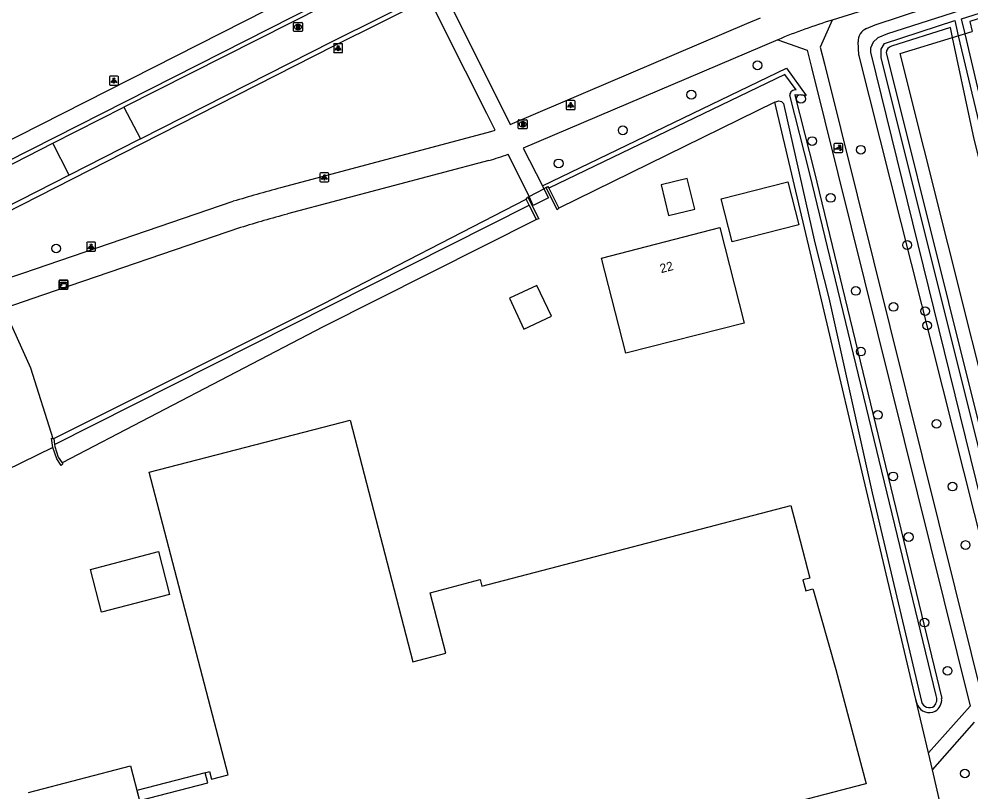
# Model space of a CAD drawing. Extents: x 162880 to 165536, y 384011 to 385179.
# Drawn here: x 163466 to 163572.4, y 384360.2 to 384446.6 of the extents above; entities that cross this region are included whole.
import ezdxf

# ---------------------------------------------------------------- set-up
doc = ezdxf.new("R2010")
doc.units = 0
for name, color, linetype in [('IMGEO_Boom', 7, 'Continuous'), ('IMGEO_Brandkraan', 7, 'Continuous'), ('IMGEO_Erf', 7, 'Continuous'), ('IMGEO_Groenvoorziening', 7, 'Continuous'), ('IMGEO_Hek', 7, 'Continuous'), ('IMGEO_Kast', 7, 'Continuous'), ('IMGEO_Lichtpunt', 7, 'Continuous'), ('IMGEO_Loofbos', 7, 'Continuous'), ('IMGEO_Muur', 7, 'Continuous'), ('IMGEO_Pand', 7, 'Continuous'), ('IMGEO_Pand_nummerreeks', 7, 'Continuous'), ('IMGEO_Pand_overbouw', 7, 'Continuous'), ('IMGEO_Poller', 7, 'Continuous'), ('IMGEO_Rijbaan_lokaal_gesloten', 7, 'Continuous'), ('IMGEO_Rijbaan_lokaal_open', 7, 'Continuous'), ('IMGEO_Rioolput', 7, 'Continuous'), ('IMGEO_Voetpad_open', 7, 'Continuous'), ('IMGEO_Waterloop', 7, 'Continuous')]:
    doc.layers.add(name, color=color, linetype=linetype)

msp = doc.modelspace()

# ---------------------------------------------------------------- linework, layer by layer
at = {"layer": 'IMGEO_Boom'}
for centre in [(163548.54, 384441.38), (163541.14, 384438.1), (163553.39, 384437.65), (163533.48, 384434.12), (163554.64, 384432.92), (163560.07, 384431.95), (163526.32, 384430.42), (163556.71, 384426.56), (163470.19, 384420.91), (163565.24, 384421.3), (163559.51, 384416.17), (163563.73, 384414.38), (163567.26, 384413.91), (163567.49, 384412.3), (163560.09, 384409.39), (163561.97, 384402.31), (163568.54, 384401.32), (163563.7, 384395.44), (163570.31, 384394.3), (163565.42, 384388.67), (163571.78, 384387.77), (163567.18, 384379.1), (163569.77, 384373.71), (163571.7, 384362.23)]:
    msp.add_circle(centre, 0.489, dxfattribs=at)
at = {"layer": 'IMGEO_Brandkraan'}
for p, q in [((163521.81, 384434.36), (163521.81, 384435.22)), ((163521.88, 384435.29), (163522.74, 384435.29)), ((163522.3, 384435.07), (163522.32, 384435.07)), ((163522.81, 384435.22), (163522.81, 384434.36)), ((163522.74, 384434.29), (163521.88, 384434.29)), ((163522.32, 384434.51), (163522.29, 384434.51))]:
    msp.add_line(p, q, dxfattribs=at)
for points in [[(163521.81, 384434.36), (163521.81, 384435.22)], [(163521.88, 384435.29), (163522.74, 384435.29)], [(163522.16, 384434.99), (163522.16, 384434.59), (163522.37, 384434.59)], [(163522.39, 384434.99), (163522.16, 384434.99)], [(163522.33, 384434.91), (163522.28, 384434.91), (163522.28, 384434.83)], [(163522.81, 384435.22), (163522.81, 384434.36)], [(163522.74, 384434.29), (163521.88, 384434.29)], [(163522.28, 384434.83), (163522.33, 384434.83)], [(163522.34, 384434.76), (163522.28, 384434.76), (163522.28, 384434.68)], [(163522.28, 384434.68), (163522.34, 384434.68)]]:
    msp.add_lwpolyline(points, dxfattribs=at)
for centre, radius, start, end in [((163521.88, 384435.22), 0.0765, 91.552, 178.448), ((163521.88, 384435.22), 0.0765, 91.552, 178.448), ((163522.34, 384434.87), 0.0379, 267.8285, 90.9355), ((163522.39, 384434.85), 0.145, 59.4692, 91.5367), ((163522.42, 384434.89), 0.0922, 285.5137, 58.1501), ((163522.73, 384435.22), 0.0765, 1.552, 88.448), ((163522.73, 384435.22), 0.0765, 1.552, 88.448), ((163521.88, 384434.37), 0.0765, 181.552, 268.448), ((163521.88, 384434.37), 0.0765, 181.552, 268.448), ((163522.34, 384434.72), 0.0404, 269.8759, 90.5077), ((163522.37, 384434.84), 0.251, 268.6676, 293.5347), ((163522.42, 384434.7), 0.105, 301.3115, 78.989), ((163522.73, 384434.37), 0.0765, 271.552, 358.448), ((163522.73, 384434.37), 0.0765, 271.552, 358.448)]:
    msp.add_arc(centre, radius, start, end, dxfattribs=at)
for centre, major_axis, ratio, start_param, end_param in [((163522.3, 384434.79), (-0.387, 0.002), 0.722429, 4.712389, 7.853982), ((163522.32, 384434.79), (-0.39, 0.002), 0.717154, 1.570796, 4.712389)]:
    msp.add_ellipse(centre, major_axis=major_axis, ratio=ratio, start_param=start_param, end_param=end_param, dxfattribs=at)
at = {"layer": 'IMGEO_Erf'}
for points in [[(163566.22, 384370.51), (163550.47, 384437.26)], [(163524.93, 384427.71), (163524.68, 384427.58)]]:
    msp.add_lwpolyline(points, dxfattribs=at)
at = {"layer": 'IMGEO_Groenvoorziening'}
for points in [[(163560.72, 384445.49), (163561.66, 384445.91), (163570.4, 384448.83), (163570.82, 384448.97), (163588.15, 384454.77), (163611.8, 384462.29), (163663.84, 384478.36), (163664.3, 384476.91), (163664.74, 384475.57), (163612.83, 384459.16), (163572.24, 384446.29), (163572.52, 384445.16)], [(163570.32, 384444.49), (163570.08, 384445.6), (163563.5, 384443.52)], [(163573.94, 384386.72), (163559.88, 384442.43), (163559.87, 384442.56), (163559.77, 384443.99)], [(163562.91, 384442.83), (163576.82, 384386.93)]]:
    msp.add_lwpolyline(points, dxfattribs=at)
for centre, radius, start, end in [((163561.35, 384444.04), 1.58, 113.5312, 181.7885), ((163563.75, 384442.7), 0.857, 107.2347, 171.5627)]:
    msp.add_arc(centre, radius, start, end, dxfattribs=at)
at = {"layer": 'IMGEO_Hek'}
for points in [[(163580.53, 384378.7), (163564.48, 384442.71), (163570.32, 384444.49)], [(163570.32, 384444.49), (163572.52, 384445.16)]]:
    msp.add_lwpolyline(points, dxfattribs=at)
at = {"layer": 'IMGEO_Kast'}
for p, q in [((163470.51, 384416.45), (163470.51, 384417.29)), ((163470.51, 384417.29), (163470.51, 384416.45)), ((163470.59, 384417.37), (163471.43, 384417.37)), ((163471.43, 384417.37), (163470.59, 384417.37)), ((163471.51, 384417.3), (163471.51, 384416.46)), ((163471.51, 384416.46), (163471.51, 384417.3)), ((163471.44, 384416.37), (163470.6, 384416.37)), ((163470.6, 384416.37), (163471.44, 384416.37))]:
    msp.add_line(p, q, dxfattribs=at)
for points in [[(163470.71, 384417.16), (163471.31, 384417.16), (163471.31, 384417.08), (163470.71, 384417.08), (163470.71, 384417.16)], [(163470.71, 384416.99), (163471.31, 384416.99), (163471.31, 384416.5), (163470.71, 384416.5), (163470.71, 384416.99)]]:
    msp.add_lwpolyline(points, dxfattribs=at)
msp.add_circle((163470.79, 384416.83), 0.0377, dxfattribs=at)
for centre, start, end in [((163470.59, 384417.29), 92.4484, 184.2845), ((163470.59, 384417.29), 92.4484, 184.2845), ((163471.43, 384417.29), 2.4484, 94.2845), ((163471.43, 384417.29), 2.4484, 94.2845), ((163470.59, 384416.45), 182.4484, 274.2845), ((163470.59, 384416.45), 182.4484, 274.2845), ((163471.43, 384416.45), 272.4484, 4.2845), ((163471.43, 384416.45), 272.4484, 4.2845)]:
    msp.add_arc(centre, 0.0779, start, end, dxfattribs=at)
at = {"layer": 'IMGEO_Lichtpunt'}
for p, q in [((163501.19, 384443.7), (163501.19, 384442.9)), ((163501.19, 384443.7), (163501.19, 384442.9)), ((163502.09, 384443.8), (163501.28, 384443.8)), ((163502.09, 384443.8), (163501.28, 384443.8)), ((163502.18, 384442.9), (163502.18, 384443.7)), ((163502.18, 384442.9), (163502.18, 384443.7)), ((163501.28, 384442.8), (163502.09, 384442.8)), ((163501.28, 384442.8), (163502.09, 384442.8)), ((163477.04, 384440.18), (163476.23, 384440.18)), ((163477.04, 384440.18), (163476.23, 384440.18)), ((163476.14, 384440.08), (163476.14, 384439.27)), ((163476.14, 384440.08), (163476.14, 384439.27)), ((163476.23, 384439.18), (163477.04, 384439.18)), ((163476.23, 384439.18), (163477.04, 384439.18)), ((163477.14, 384439.27), (163477.14, 384440.08)), ((163477.14, 384439.27), (163477.14, 384440.08)), ((163527.16, 384437.34), (163527.16, 384436.53)), ((163527.16, 384437.34), (163527.16, 384436.53)), ((163528.06, 384437.44), (163527.25, 384437.44)), ((163528.06, 384437.44), (163527.25, 384437.44)), ((163528.15, 384436.53), (163528.15, 384437.34)), ((163528.15, 384436.53), (163528.15, 384437.34)), ((163527.25, 384436.44), (163528.06, 384436.44)), ((163527.25, 384436.44), (163528.06, 384436.44)), ((163499.65, 384429.26), (163499.65, 384428.45)), ((163499.65, 384429.26), (163499.65, 384428.45)), ((163500.55, 384429.35), (163499.74, 384429.35)), ((163500.55, 384429.35), (163499.74, 384429.35)), ((163500.64, 384428.45), (163500.64, 384429.26)), ((163500.64, 384428.45), (163500.64, 384429.26)), ((163499.74, 384428.36), (163500.55, 384428.36)), ((163499.74, 384428.36), (163500.55, 384428.36)), ((163473.6, 384421.51), (163473.6, 384420.7)), ((163473.6, 384421.51), (163473.6, 384420.7)), ((163474.5, 384421.6), (163473.69, 384421.6)), ((163474.5, 384421.6), (163473.69, 384421.6)), ((163474.59, 384420.7), (163474.59, 384421.51)), ((163474.59, 384420.7), (163474.59, 384421.51)), ((163473.69, 384420.61), (163474.5, 384420.61)), ((163473.69, 384420.61), (163474.5, 384420.61))]:
    msp.add_line(p, q, dxfattribs=at)
for points in [[(163501.56, 384443.37), (163501.6, 384443.34), (163501.41, 384443.08), (163501.37, 384443.11), (163501.56, 384443.37)], [(163501.77, 384443.34), (163501.81, 384443.37), (163502, 384443.1), (163501.96, 384443.08), (163501.77, 384443.34)], [(163501.66, 384443.32), (163501.71, 384443.32), (163501.71, 384443), (163501.66, 384443), (163501.66, 384443.32)], [(163476.51, 384439.74), (163476.55, 384439.72), (163476.36, 384439.45), (163476.33, 384439.48), (163476.51, 384439.74)], [(163476.61, 384439.7), (163476.66, 384439.7), (163476.66, 384439.37), (163476.61, 384439.37), (163476.61, 384439.7)], [(163476.72, 384439.72), (163476.76, 384439.74), (163476.95, 384439.48), (163476.91, 384439.45), (163476.72, 384439.72)], [(163527.53, 384437), (163527.57, 384436.98), (163527.38, 384436.71), (163527.34, 384436.74), (163527.53, 384437)], [(163527.74, 384436.98), (163527.78, 384437), (163527.97, 384436.74), (163527.93, 384436.71), (163527.74, 384436.98)], [(163527.63, 384436.96), (163527.68, 384436.96), (163527.68, 384436.63), (163527.63, 384436.63), (163527.63, 384436.96)], [(163500.02, 384428.92), (163500.06, 384428.89), (163499.87, 384428.63), (163499.83, 384428.66), (163500.02, 384428.92)], [(163500.12, 384428.87), (163500.17, 384428.87), (163500.17, 384428.55), (163500.12, 384428.55), (163500.12, 384428.87)], [(163500.23, 384428.89), (163500.27, 384428.92), (163500.46, 384428.66), (163500.42, 384428.63), (163500.23, 384428.89)], [(163473.97, 384421.17), (163474.01, 384421.15), (163473.82, 384420.88), (163473.78, 384420.91), (163473.97, 384421.17)], [(163474.07, 384421.13), (163474.12, 384421.13), (163474.12, 384420.8), (163474.07, 384420.8), (163474.07, 384421.13)], [(163474.18, 384421.15), (163474.22, 384421.17), (163474.41, 384420.91), (163474.37, 384420.88), (163474.18, 384421.15)]]:
    msp.add_lwpolyline(points, dxfattribs=at)
for centre in [(163501.69, 384443.5), (163476.64, 384439.88), (163527.66, 384437.14), (163500.15, 384429.06), (163474.1, 384421.31)]:
    msp.add_circle(centre, 0.0994, dxfattribs=at)
for centre, start, end in [((163501.28, 384443.7), 90, 180), ((163501.28, 384443.7), 90, 180), ((163502.09, 384443.7), 0, 90), ((163502.09, 384443.7), 0, 90), ((163501.28, 384442.9), 180, 270), ((163501.28, 384442.9), 180, 270), ((163502.09, 384442.9), 270, 0), ((163502.09, 384442.9), 270, 360), ((163476.23, 384440.08), 90, 180), ((163476.23, 384440.08), 90, 180), ((163477.04, 384440.08), 0, 90), ((163477.04, 384440.08), 0, 90), ((163476.23, 384439.27), 180, 270), ((163476.23, 384439.27), 180, 270), ((163477.04, 384439.27), 270, 0), ((163477.04, 384439.27), 270, 360), ((163527.25, 384437.34), 90, 180), ((163527.25, 384437.34), 90, 180), ((163528.06, 384437.34), 0, 90), ((163528.06, 384437.34), 0, 90), ((163527.25, 384436.53), 180, 270), ((163527.25, 384436.53), 180, 270), ((163528.06, 384436.53), 270, 0), ((163528.06, 384436.53), 270, 360), ((163499.74, 384429.26), 90, 180), ((163499.74, 384429.26), 90, 180), ((163500.55, 384429.26), 0, 90), ((163500.55, 384429.26), 0, 90), ((163499.74, 384428.45), 180, 270), ((163499.74, 384428.45), 180, 270), ((163500.55, 384428.45), 270, 0), ((163500.55, 384428.45), 270, 360), ((163473.69, 384421.51), 90, 180), ((163473.69, 384421.51), 90, 180), ((163474.5, 384421.51), 0, 90), ((163474.5, 384421.51), 0, 90), ((163473.69, 384420.7), 180, 270), ((163473.69, 384420.7), 180, 270), ((163474.5, 384420.7), 270, 0), ((163474.5, 384420.7), 270, 360)]:
    msp.add_arc(centre, 0.0946, start, end, dxfattribs=at)
at = {"layer": 'IMGEO_Loofbos'}
for points in [[(163595.6, 384318.9), (163580.53, 384378.7), (163564.48, 384442.71), (163570.32, 384444.49)], [(163595.6, 384318.9), (163599.51, 384318.97), (163598.25, 384321.03), (163592.32, 384348.74), (163591.99, 384351.3), (163592, 384352.86), (163592.17, 384354.25), (163592.74, 384356.46), (163593.36, 384359.55), (163593.66, 384362.14), (163590.08, 384376.56), (163588.8, 384381.41), (163587.18, 384383.07), (163586.46, 384383.8), (163584.58, 384385.81), (163572.73, 384433.13), (163570.32, 384444.49)], [(163524.51, 384427.9), (163551.78, 384441.06), (163553.97, 384438.01), (163552.76, 384438.09)], [(163552.7, 384438.06), (163554.88, 384429.55), (163569.11, 384370.61)], [(163469.92, 384399.66), (163500, 384414.74), (163522.7, 384426.42)], [(163523.01, 384426.71), (163522.87, 384426.64)], [(163566.41, 384369.92), (163566.22, 384370.51)], [(163567.63, 384364.53), (163566.22, 384370.51)], [(163569.03, 384358.6), (163568.07, 384362.66)]]:
    msp.add_lwpolyline(points, dxfattribs=at)
for centre, radius, start, end in [((163552.76, 384438), 0.0861, 92.1457, 140.2545), ((163567.6, 384370.5), 1.51, 301.1147, 4.201), ((163567.74, 384370.48), 1.44, 203.0341, 296.9017)]:
    msp.add_arc(centre, radius, start, end, dxfattribs=at)
at = {"layer": 'IMGEO_Muur'}
for points in [[(163524.93, 384427.71), (163525.13, 384427.84), (163525.23, 384427.64)], [(163526.35, 384425.41), (163526.17, 384425.24), (163524.93, 384427.71)], [(163525.23, 384427.64), (163526.35, 384425.41)], [(163522.7, 384426.42), (163522.87, 384426.64)], [(163523.04, 384425.75), (163522.7, 384426.42)], [(163522.87, 384426.64), (163524.09, 384424.21), (163523.86, 384424.15)], [(163523.86, 384424.15), (163523.04, 384425.75)], [(163469.82, 384398.68), (163469.67, 384399.73), (163469.8, 384399.69)], [(163469.8, 384399.69), (163469.92, 384399.66)], [(163469.92, 384399.66), (163470, 384399.01)], [(163470, 384399.01), (163470.03, 384398.78), (163470.42, 384397.59), (163470.87, 384396.97)], [(163470.87, 384396.97), (163470.95, 384396.85), (163470.74, 384396.67), (163470.26, 384397.39), (163469.82, 384398.68)]]:
    msp.add_lwpolyline(points, dxfattribs=at)
at = {"layer": 'IMGEO_Pand'}
for points in [[(163538.61, 384424.6), (163541.52, 384425.31), (163540.69, 384428.72), (163537.78, 384428.01), (163538.61, 384424.6)], [(163545.72, 384421.66), (163544.49, 384426.47), (163551.92, 384428.37), (163553.15, 384423.57), (163545.72, 384421.66)], [(163531.12, 384419.82), (163544.32, 384423.24), (163547.03, 384412.56), (163533.82, 384409.2), (163531.12, 384419.82)], [(163525.51, 384413.33), (163523.89, 384416.78), (163520.83, 384415.35), (163522.45, 384411.9), (163525.51, 384413.33)], [(163467.11, 384360.12), (163478.49, 384363.09), (163479.5, 384359.22), (163487.12, 384361.2), (163486.83, 384362.33), (163487.32, 384362.46), (163487.54, 384361.59), (163489.39, 384362.07), (163480.58, 384395.9), (163500, 384400.96), (163503.02, 384401.74), (163510.05, 384374.73), (163513.71, 384375.69), (163511.95, 384382.43), (163517.57, 384383.9), (163517.75, 384383.18), (163552.26, 384392.19), (163553.29, 384388.25), (163554.38, 384384.08), (163553.6, 384383.87), (163553.92, 384382.67), (163554.71, 384382.88), (163554.78, 384382.66), (163557.27, 384373.86), (163560.67, 384361.1), (163560.48, 384361.05), (163500, 384345.3)], [(163475.26, 384380.27), (163474.01, 384385.05), (163481.62, 384387.03), (163482.86, 384382.25), (163475.26, 384380.27)]]:
    msp.add_lwpolyline(points, dxfattribs=at)
at = {"layer": 'IMGEO_Pand_overbouw'}
msp.add_lwpolyline([(163486.83, 384362.33), (163479.21, 384360.34), (163479.5, 384359.22), (163487.12, 384361.2)], close=True, dxfattribs=at)
at = {"layer": 'IMGEO_Poller'}
for p, q in [((163557.06, 384432.55), (163557.06, 384431.75)), ((163557.06, 384432.55), (163557.06, 384431.75)), ((163557.96, 384432.65), (163557.16, 384432.65)), ((163557.96, 384432.65), (163557.16, 384432.65)), ((163557.16, 384431.65), (163557.96, 384431.65)), ((163557.16, 384431.65), (163557.96, 384431.65)), ((163558.06, 384431.75), (163558.06, 384432.55)), ((163558.06, 384431.75), (163558.06, 384432.55))]:
    msp.add_line(p, q, dxfattribs=at)
for points in [[(163557.7, 384432.01), (163557.18, 384432.01), (163557.61, 384432.28)], [(163557.74, 384432.38), (163557.73, 384432.31), (163557.6, 384432.51)], [(163557.6, 384432.51), (163557.83, 384432.44), (163557.76, 384432.41)], [(163557.76, 384431.83), (163557.82, 384432.06), (163557.85, 384432)], [(163557.89, 384431.97), (163557.96, 384431.96), (163557.76, 384431.83)]]:
    msp.add_lwpolyline(points, dxfattribs=at)
for centre, radius, start, end in [((163557.16, 384432.55), 0.0946, 90, 180), ((163557.16, 384432.55), 0.0946, 90, 180), ((163557.16, 384431.75), 0.0946, 180, 270), ((163557.16, 384431.75), 0.0946, 180, 270), ((163557.37, 384432.06), 0.332, 351.3247, 42.4854), ((163557.38, 384432.06), 0.476, 351.7527, 41.1691), ((163557.38, 384432.06), 0.516, 349.3569, 42.2912), ((163557.96, 384432.55), 0.0946, 0, 90), ((163557.96, 384432.55), 0.0946, 0, 90), ((163557.96, 384431.75), 0.0946, 270, 0), ((163557.96, 384431.75), 0.0946, 270, 0)]:
    msp.add_arc(centre, radius, start, end, dxfattribs=at)
at = {"layer": 'IMGEO_Rijbaan_lokaal_gesloten'}
for points in [[(163533.89, 384463.7), (163515.62, 384455.64), (163512.12, 384454.06), (163507.53, 384451.79), (163477.73, 384436.72)], [(163479.61, 384433.16), (163501.03, 384444.03), (163511.58, 384449.35), (163513.3, 384450.16), (163514.59, 384450.8), (163524.26, 384455.15), (163531.82, 384458.48)], [(163469.82, 384432.67), (163477.73, 384436.72)], [(163477.73, 384436.72), (163479.61, 384433.16)], [(163479.61, 384433.16), (163479.38, 384433.04), (163471.64, 384429.1)], [(163374.59, 384385.06), (163378.92, 384387.01), (163383.95, 384389.29), (163393.3, 384393.9), (163393.86, 384394.17), (163406.16, 384400.32), (163431.17, 384413.02), (163456.86, 384426.07), (163469.82, 384432.67)], [(163471.64, 384429.1), (163469.82, 384432.67)], [(163471.64, 384429.1), (163456.94, 384421.62), (163434.92, 384410.46), (163407.23, 384396.42), (163398.13, 384391.86), (163397.11, 384391.35), (163394.25, 384389.94)]]:
    msp.add_lwpolyline(points, dxfattribs=at)
at = {"layer": 'IMGEO_Rijbaan_lokaal_open'}
for points in [[(163533.67, 384464.15), (163515.41, 384456.1), (163511.93, 384454.51), (163507.29, 384452.24), (163456.62, 384426.53), (163430.98, 384413.5), (163405.97, 384400.81), (163393.64, 384394.66), (163392.99, 384394.34), (163383.77, 384389.8), (163378.73, 384387.48), (163374.46, 384385.55)], [(163462.47, 384423.87), (163479.69, 384432.62), (163501.21, 384443.55), (163511.84, 384448.9)], [(163464.33, 384414.22), (163467.33, 384407.56), (163469.8, 384399.69)], [(163469.82, 384398.68), (163464.57, 384396.09)]]:
    msp.add_lwpolyline(points, dxfattribs=at)
at = {"layer": 'IMGEO_Rioolput'}
for p, q in [((163496.71, 384445.24), (163496.71, 384446.1)), ((163496.78, 384446.17), (163497.63, 384446.17)), ((163497.19, 384445.95), (163497.22, 384445.95)), ((163497.71, 384446.1), (163497.71, 384445.24)), ((163497.63, 384445.17), (163496.78, 384445.17)), ((163497.22, 384445.39), (163497.19, 384445.39))]:
    msp.add_line(p, q, dxfattribs=at)
for points in [[(163496.71, 384445.24), (163496.71, 384446.1)], [(163496.78, 384446.17), (163497.63, 384446.17)], [(163497.29, 384445.87), (163497.04, 384445.87), (163497.04, 384445.47)], [(163497.04, 384445.47), (163497.17, 384445.47), (163497.17, 384445.63), (163497.18, 384445.63)], [(163497.22, 384445.79), (163497.17, 384445.79), (163497.17, 384445.71)], [(163497.17, 384445.71), (163497.22, 384445.71)], [(163497.22, 384445.6), (163497.3, 384445.47), (163497.43, 384445.47), (163497.37, 384445.6)], [(163497.71, 384446.1), (163497.71, 384445.24)], [(163497.63, 384445.17), (163496.78, 384445.17)]]:
    msp.add_lwpolyline(points, dxfattribs=at)
for centre, radius, start, end in [((163496.78, 384446.1), 0.0765, 91.552, 178.448), ((163496.78, 384446.1), 0.0765, 91.552, 178.448), ((163497.18, 384445.58), 0.0533, 26.0293, 88.6989), ((163497.23, 384445.69), 0.0964, 77.0061, 93.1865), ((163497.2, 384445.9), 0.19, 274.7715, 282.9687), ((163497.24, 384445.75), 0.0378, 276.6634, 79.6772), ((163497.29, 384445.76), 0.109, 350.3612, 89.416), ((163497.29, 384445.76), 0.112, 277.5842, 350.9817), ((163497.28, 384445.54), 0.108, 29.5134, 73.7905), ((163497.63, 384446.1), 0.0765, 1.552, 88.448), ((163497.63, 384446.1), 0.0765, 1.552, 88.448), ((163496.78, 384445.25), 0.0765, 181.552, 268.448), ((163496.78, 384445.25), 0.0765, 181.552, 268.448), ((163497.63, 384445.25), 0.0765, 271.552, 358.448), ((163497.63, 384445.25), 0.0765, 271.552, 358.448)]:
    msp.add_arc(centre, radius, start, end, dxfattribs=at)
for centre, major_axis, ratio, start_param, end_param in [((163497.19, 384445.67), (-0.387, 0.002), 0.722429, 4.712389, 7.853982), ((163497.22, 384445.67), (-0.39, 0.002), 0.717154, 1.570796, 4.712389)]:
    msp.add_ellipse(centre, major_axis=major_axis, ratio=ratio, start_param=start_param, end_param=end_param, dxfattribs=at)
at = {"layer": 'IMGEO_Voetpad_open'}
for points in [[(163455.22, 384428.07), (163455.74, 384428.34), (163506.36, 384454.02), (163510.84, 384456.22), (163514.55, 384458), (163519.9, 384460.32), (163524.59, 384462.42), (163537.83, 384468.23), (163538.68, 384466.28)], [(163590.73, 384457.04), (163589.83, 384456.78), (163568.94, 384450.23), (163556.87, 384446.42)], [(163495.27, 384427.71), (163517.76, 384433.71), (163518.74, 384433.99), (163519.22, 384434.14), (163518.28, 384435.99), (163513.54, 384445.45), (163511.84, 384448.9)], [(163513.51, 384449.7), (163514.81, 384446.98), (163520, 384436.58), (163520.9, 384434.77), (163524.02, 384436.11), (163547.35, 384446.04), (163548.87, 384446.69)], [(163556.87, 384446.42), (163555.55, 384443.43), (163556.02, 384441.54), (163574.23, 384368.32)], [(163550.82, 384444.23), (163522.36, 384432.12), (163524.51, 384427.9)], [(163550.82, 384444.23), (163554.07, 384443.08), (163554.55, 384441.15), (163572.29, 384369.75), (163567.63, 384364.53)], [(163518.53, 384430.76), (163496.04, 384424.77)], [(163523.01, 384426.71), (163520.67, 384431.44)], [(163523.01, 384426.71), (163524.68, 384427.58)], [(163524.68, 384427.58), (163525.18, 384426.58), (163523.49, 384425.73), (163523.01, 384426.71)], [(163524.51, 384427.9), (163524.68, 384427.58)], [(163463.06, 384417.05), (163466.47, 384418.15), (163489.96, 384426.19)], [(163490.78, 384423.25), (163468.76, 384415.74), (163464.33, 384414.22)], [(163568.07, 384362.66), (163572.76, 384367.96)], [(163568.07, 384362.66), (163567.63, 384364.53)]]:
    msp.add_lwpolyline(points, dxfattribs=at)
for centre, radius, start, end in [((163573.3, 384391.49), 57.34, 106.6549, 113.0876), ((163511.57, 384456.26), 26.44, 285.2748, 290.1426), ((163577.27, 384130.38), 308.42, 105.4181, 106.4442), ((163533.98, 384283.02), 146.73, 104.9834, 107.1228)]:
    msp.add_arc(centre, radius, start, end, dxfattribs=at)
at = {"layer": 'IMGEO_Waterloop'}
for points in [[(163662.63, 384476.79), (163563.06, 384444.92), (163561.99, 384444.45), (163561.47, 384443.98), (163561.14, 384443.3), (163561.14, 384442.85), (163574.69, 384387.89)], [(163585.07, 384388.06), (163571.72, 384444.91), (163571.33, 384446.56), (163663.4, 384475.66)], [(163575.85, 384388.18), (163562.33, 384442.22), (163562.33, 384443.17), (163562.71, 384443.82), (163570.56, 384446.38), (163570.96, 384444.68), (163584.85, 384386.42)], [(163552.85, 384438.63), (163551.6, 384440.37), (163525.23, 384427.64)], [(163568.49, 384370.95), (163554.35, 384429.41), (163552.13, 384438.06)], [(163550.47, 384437.26), (163526.35, 384425.41)], [(163550.47, 384437.26), (163550.92, 384437.4), (163551.23, 384437.35), (163551.43, 384437.1), (163554.95, 384421.55), (163556.49, 384415.41), (163561.35, 384393.6), (163566.87, 384370.27)], [(163470, 384399.01), (163523.04, 384425.75)], [(163523.86, 384424.15), (163500, 384412.17), (163470.87, 384396.97)]]:
    msp.add_lwpolyline(points, dxfattribs=at)
for centre, radius, start, end in [((163552.76, 384438.01), 0.632, 81.7349, 175.0979), ((163567.73, 384370.48), 0.886, 193.5469, 306.3675), ((163567.46, 384370.54), 1.11, 316.0281, 21.7642)]:
    msp.add_arc(centre, radius, start, end, dxfattribs=at)

# ---------------------------------------------------------------- texts
at = {"layer": 'IMGEO_Pand_nummerreeks'}
msp.add_text('22', height=1, rotation=14.5648, dxfattribs=at).set_placement((163537.77, 384418.15))

doc.saveas('drawing.dxf')
